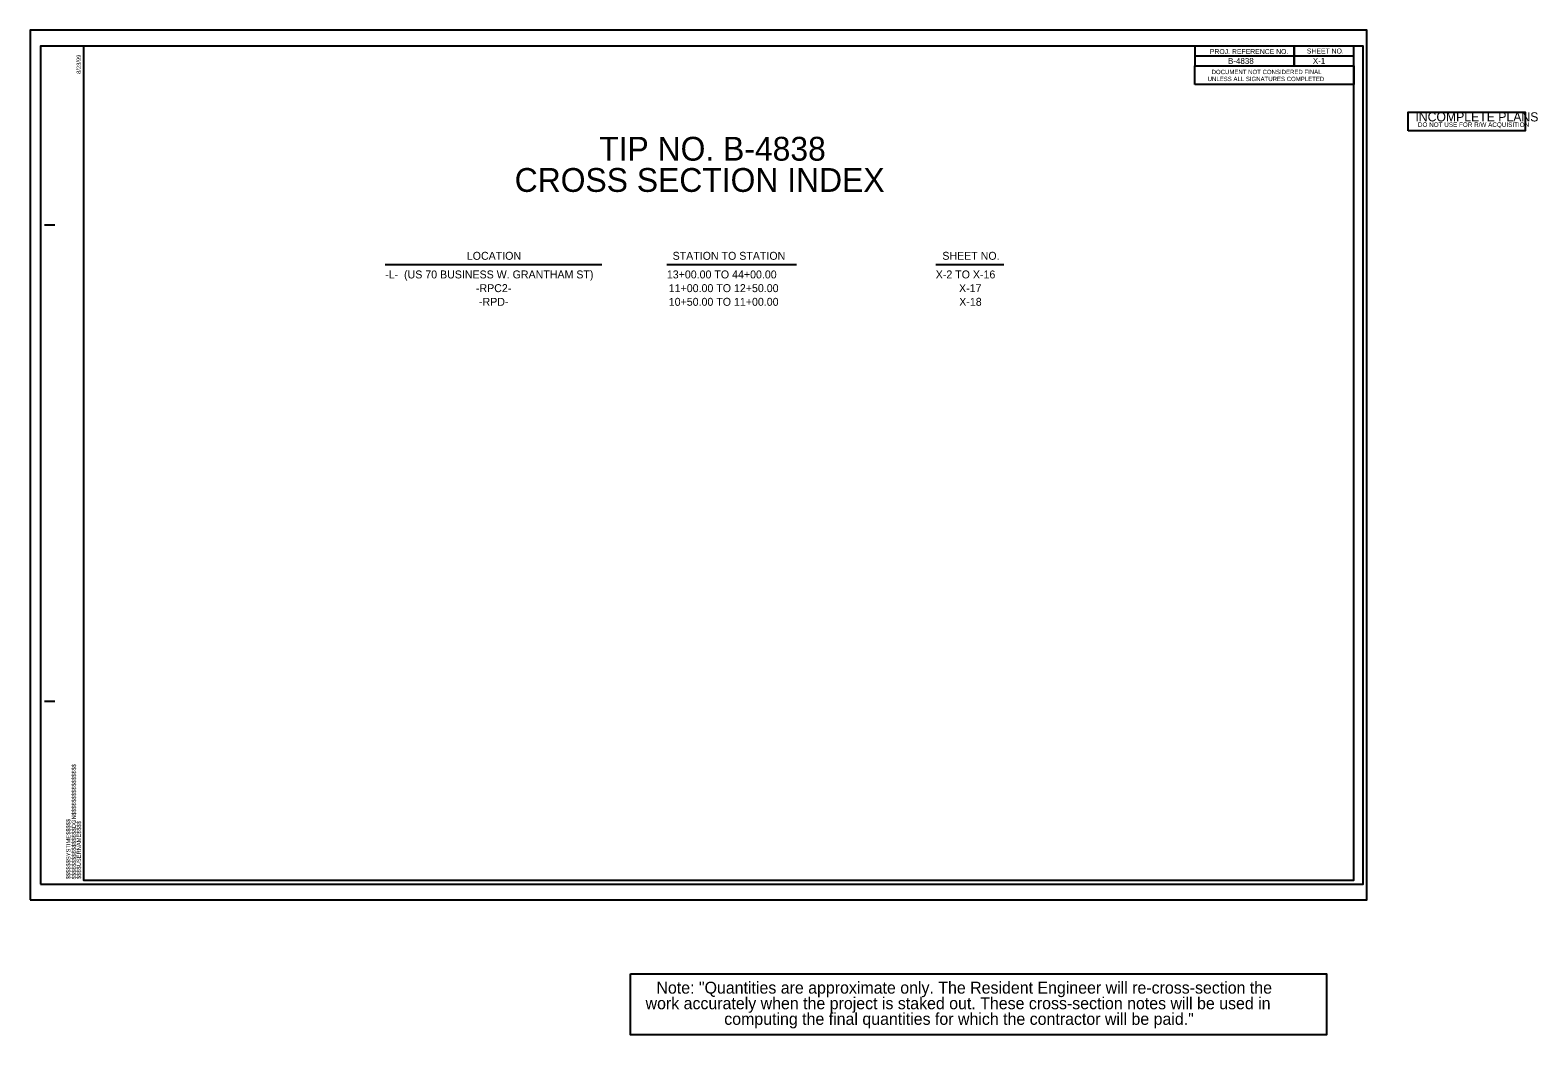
# Model space of a CAD drawing. Extents: x -13 to 366, y -39 to 214.
import ezdxf

# ---------------------------------------------------------------- set-up
doc = ezdxf.new("R2010")
doc.units = 0
for name, color, linetype in [('Default', 7, 'Continuous'), ('Prop Conc 1ft 6in Curb and Gutter', 7, 'Continuous'), ('Prop Grid Mask', 7, 'Continuous'), ('Prop XS Project Number', 7, 'Continuous'), ('Prop XS Sheet Number', 7, 'Continuous'), ('Prop XS Station Labels', 7, 'Continuous'), ('Prop XSC Text', 7, 'Continuous'), ('Sheet Cross Section CELL', 7, 'Continuous'), ('Sheet Cutting Line CELL', 7, 'Continuous'), ('Sheet Data Field CELL', 7, 'Continuous'), ('Sheet Plot Border Inside CELL', 7, 'Continuous'), ('Sheet Plot Border Outside CELL', 7, 'Continuous'), ('Sheet Sticker Incomplete CELL', 7, 'Continuous')]:
    doc.layers.add(name, color=color, linetype=linetype)

# ---------------------------------------------------------------- blocks, each defined once
blk = doc.blocks.new('STICKER INCOMPLETE PLANS')
at = {"layer": 'Sheet Sticker Incomplete CELL'}
blk.add_lwpolyline([(0, -0.47), (0, 0), (2.94, 0), (2.94, -0.47)], close=True, dxfattribs=at)
for s, height, p in [('INCOMPLETE PLANS', 0.2304, (0.179, -0.236)), ('DO NOT USE FOR R/W ACQUISITION', 0.1152, (0.244, -0.375))]:
    blk.add_text(s, height=height, dxfattribs=at).set_placement(p)

msp = doc.modelspace()

# ---------------------------------------------------------------- linework, layer by layer
at = {"layer": 'Prop Conc 1ft 6in Curb and Gutter'}
for p, q in [((280, 200.3), (280, 205)), ((280, 205), (320, 205)), ((320, 205), (320, 200.3)), ((320, 200.3), (280, 200.3))]:
    msp.add_line(p, q, dxfattribs=at)
at = {"layer": 'Prop Grid Mask'}
msp.add_lwpolyline([(137.8, -23.6), (313.15, -23.6), (313.15, -38.98), (137.8, -38.98)], close=True, dxfattribs=at)
at = {"layer": 'Prop XS Station Labels'}
for p, q in [((76.03, 155.02), (130.64, 155.02)), ((146.98, 155.02), (179.63, 155.02)), ((214.71, 155.02), (231.88, 155.02))]:
    msp.add_line(p, q, dxfattribs=at)
at = {"layer": 'Sheet Cross Section CELL'}
for p, q in [((305, 210), (305, 205)), ((305, 205), (305, 210)), ((280, 207.5), (280, 205)), ((320, 207.49), (280, 207.49)), ((280, 205), (320, 205)), ((-9.8, 165), (-7.3, 165)), ((-9.7, 165), (-7.2, 165)), ((-9.8, 45), (-7.3, 45)), ((-9.7, 45), (-7.2, 45)), ((0, 0), (0, 0)), ((0, 0), (0, 0)), ((0, 0), (0, 0)), ((0, 0), (0, 0)), ((0, 0), (0, 0)), ((0, 0), (0, 0)), ((0, 0), (0, 0))]:
    msp.add_line(p, q, dxfattribs=at)
for points in [[(320, 210), (0, 210), (0, 0), (320, 0)], [(320, 210), (280, 210), (280, 205), (320, 205)]]:
    msp.add_lwpolyline(points, close=True, dxfattribs=at)
at = {"layer": 'Sheet Cutting Line CELL'}
for p, q in [((323.3, 214), (-13.4, 214)), ((-13.4, 214), (-13.4, -5)), ((-13.4, -5), (323.3, -5))]:
    msp.add_line(p, q, dxfattribs=at)
at = {"layer": 'Sheet Plot Border Inside CELL'}
msp.add_lwpolyline([(-10.8, -1), (322.4, -1), (322.4, 210), (-10.8, 210)], close=True, dxfattribs=at)
at = {"layer": 'Sheet Plot Border Outside CELL'}
msp.add_lwpolyline([(-13.4, -5), (323.3, -5), (323.3, 214), (-13.4, 214)], close=True, dxfattribs=at)

# ---------------------------------------------------------------- block references
at = {"layer": 'Default', "xscale": 10, "yscale": 10}
msp.add_blockref('STICKER INCOMPLETE PLANS', (333.74, 193.38), dxfattribs=at)

# ---------------------------------------------------------------- texts
at = {"layer": 'Prop Conc 1ft 6in Curb and Gutter'}
for s, p in [('UNLESS ALL SIGNATURES COMPLETED', (283.2, 201.17)), ('DOCUMENT NOT CONSIDERED FINAL', (284.21, 202.93))]:
    msp.add_text(s, height=1.0998, rotation=360, dxfattribs=at).set_placement(p)
at = {"layer": 'Prop XS Project Number'}
msp.add_text('B-4838', height=1.5, dxfattribs=at).set_placement((288.34, 205.5))
at = {"layer": 'Prop XS Sheet Number'}
msp.add_text('X-1', height=1.5, dxfattribs=at).set_placement((309.7, 205.5))
at = {"layer": 'Prop XS Station Labels'}
for s, p in [('LOCATION', (96.59, 156.18)), ('STATION TO STATION', (148.43, 156.18)), ('SHEET NO.', (216.37, 156.18)), ('13+00.00 TO 44+00.00', (146.98, 151.49)), ('X-2 TO X-16', (214.71, 151.49)), ('-RPC2-', (98.89, 148.04)), ('11+00.00 TO 12+50.00', (147.46, 148.04)), ('X-17', (220.58, 148.04)), ('-RPD-', (99.66, 144.6)), ('10+50.00 TO 11+00.00', (147.46, 144.6)), ('X-18', (220.63, 144.6))]:
    msp.add_text(s, height=2, rotation=360, dxfattribs=at).set_placement(p)
msp.add_text('-L-  (US 70 BUSINESS W. GRANTHAM ST)', height=2, dxfattribs=at).set_placement((76.03, 151.49))
at = {"layer": 'Prop XSC Text'}
for s, p in [('Note: "Quantities are approximate only. The Resident Engineer will re-cross-section the', (144.36, -28.6)), ('work accurately when the project is staked out. These cross-section notes will be used in', (141.62, -32.53)), ('computing the final quantities for which the contractor will be paid."', (161.44, -36.46))]:
    msp.add_text(s, height=3, dxfattribs=at).set_placement(p)
at = {"layer": 'Sheet Cross Section CELL'}
for s, p in [('PROJ. REFERENCE NO.', (283.77, 207.99)), ('SHEET NO.', (308.19, 208.12))]:
    msp.add_text(s, height=1.25, dxfattribs=at).set_placement(p)
for s, p in [('8/23/99', (-0.65, 203)), ('$$$$$$$$$$$$$$$$DGN$$$$$$$$$$$$$$$$', (-1.88, 0.18)), ('$$$$$$SYSTIME$$$$$', (-3.26, 0.18)), ('$$$$USERNAME$$$$', (-0.62, 0.23))]:
    msp.add_text(s, height=1.05, rotation=90, dxfattribs=at).set_placement(p)
at = {"layer": 'Sheet Data Field CELL'}
for s, p in [('TIP NO. B-4838', (129.94, 181.14)), ('CROSS SECTION INDEX', (108.65, 173.28))]:
    msp.add_text(s, height=6, rotation=360, dxfattribs=at).set_placement(p)

doc.saveas('drawing.dxf')
